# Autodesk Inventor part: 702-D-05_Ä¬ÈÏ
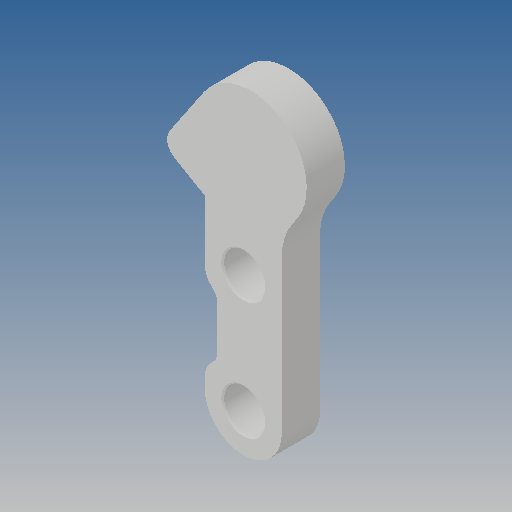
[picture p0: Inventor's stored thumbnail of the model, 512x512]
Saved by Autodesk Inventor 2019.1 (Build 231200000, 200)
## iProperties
Created: 2010-06
Part Number: 702-D-05_Ä¬ÈÏ
Material: Ogólny
Document SubType Name: Modeling
Designer: CADENGINEERING4
Density: 1 g/cm^3
Appearance: Domyślna
Author: CADENGINEERING4
Revision Number: ÈÎºÎ
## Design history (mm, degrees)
feature "NONE"
node "Bryła1"
